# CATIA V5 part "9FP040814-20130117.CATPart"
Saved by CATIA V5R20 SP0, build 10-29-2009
Part number: 9FP040814-20130117
Revision: ANY
Definition: UNKNOWN
Nomenclature: 9FP040814-20130117
Source: Unknown
Bounding box of the stored display mesh (mm): x -7 to 7, y -7 to 7, z 0 to 8
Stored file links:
  C:\Users\Utente\Desktop\IO LAVORO\3D X SITO CF\CUMSA\3D files PF\PF 0842WB\9FP040814-20130117.CATPart
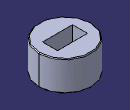
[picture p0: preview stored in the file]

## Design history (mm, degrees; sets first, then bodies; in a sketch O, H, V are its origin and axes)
Body1 "Chaflán1" (main body)
  Solid1: solid without history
